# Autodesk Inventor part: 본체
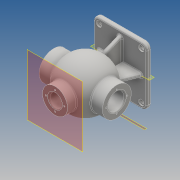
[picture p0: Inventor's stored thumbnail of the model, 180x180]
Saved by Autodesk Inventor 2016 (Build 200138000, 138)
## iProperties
Created: 2017-01
Part Number: 본체
Material: 일반
Document SubType Name: Modeling
Designer: Administrator
Density: 1 g/cm^3
Appearance: 기본값
Author: Administrator
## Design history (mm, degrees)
sketch "스케치1"
  geometry: L1 (57.5, 62.5)-(-57.5, 62.5); L2 (-57.5, 62.5)-(-57.5, -62.5); L3 (-57.5, -62.5)-(57.5, -62.5); L4 (57.5, -62.5)-(57.5, 62.5); L5 (57.5, 62.5)-(-57.5, -62.5); L6 (-57.5, 62.5)-(57.5, -62.5); 1 further point
  constraints: 12 end point, 2 midpoint, 2 parallel, 1 horizontal, 1 perpendicular
  dimensions: "d0" = 125 distance between parallel lines of L3 L1; "d1" = 115 distance between parallel lines of L2 L4
extrude "돌출1" new body sketch "스케치1" distance "d2" = 10; taper "d3" = 0 deg
fillet "모깎기2" dims "d5" = 3
fillet "모깎기3" dims "d6" = 12
node "작업 평면1"
sketch "스케치5"
  geometry: L1 (113.5, -75)-(-22.5, -75); L2 (113.5, -75)-(113.5, -106); L3 (-22.5, -75)-(-22.5, -106); L4 (45.5, 0)-(45.5, -185.881); L5 (113.5, -106)-(88.488, -106); L6 (-22.5, -106)-(2.512, -106); L7 (113.5, -92.5)-(84.778, -92.5); L8 (-22.5, -92.5)-(-6.5, -92.5); L9 (-6.5, -92.5)-(-6.5, -93.5); L10 (-6.5, -93.5)-(-4.75, -93.5); L11 (-4.75, -93.5)-(-4.75, -92.5); L12 (-4.75, -92.5)-(6.222, -92.5); L13 (0, 10)-(91, 10) reference; A1 r 53 centre (45.5, -75) between (2.512, -106) and (88.488, -106); A2 r 43 centre (45.5, -75) between (6.222, -92.5) and (84.778, -92.5)
  constraints: 24 end point, 5 horizontal, 4 point on circle, 4 point on line, 3 perpendicular, 3 vertical, 2 centre point, 1 coincident, 1 midpoint
  dimensions: "d22" = 136 distance between parallel lines of L3 L2; "d27" = 31 distance from line of L2.end L1; "d30" = 53 radius of A1; "d31" = 43 radius of A2; "d32" = 16 distance between parallel lines of L9 L3; "d33" = 17.5 distance between parallel lines of L1 L8; "d34" = 18.5 distance between parallel lines of L1 L10; "d35" = 17.5 distance between parallel lines of L7 L1; "d36" = 17.5 distance from line of L1 L12.end; "d37" = 31 distance between parallel lines of L6 L1; "d38" = 1.75 distance between parallel lines of L11 L9; "d39" = 85 distance between parallel lines of L13 L1
revolve "회전1" sketch "스케치5" stored, may be unused: angle "d40" = 90 deg
sketch "스케치6" dims "d41" = 48
  geometry: 3 further points
  constraints: 1 vertical alignment, 2 other
hole "구멍2" sketch "스케치6" at (0, -24) diameter "d42" = 3.242; stored, may be unused: countersink angle "d46" = 90 deg, drill point angle "d48" = 118 deg; dims "d43" = 16, "d44" = 12, "d45" = 3, "d47" = 19
node "작업 평면2"
sketch "스케치8"
  geometry: C1 r 27 at (0, 0); 1 further point
  constraints: 1 centre point, 1 coincident
  dimensions: "d61" = 54 diameter of C1
extrude "돌출2" join sketch "스케치8" stored distance "d62" = 10; taper "d63" = 0 deg
sketch "스케치9"
  geometry: C1 r 13 at (0, 0); 1 further point
  constraints: 1 centre point, 1 coincident
  dimensions: "d64" = 26 diameter of C1
extrude "돌출3" cut sketch "스케치9" distance "d65" = 50; taper "d66" = 0 deg
sketch "스케치10"
  geometry: A1 r 20 centre (0, 0) between (0, -20) and (0, 20); 3 further points
  constraints: 4 point on circle, 1 centre point, 1 coincident
  dimensions: "d67" = 40 diameter of A1
hole "구멍3" sketch "스케치10" at (0, -20), (20, 0), (0, 20), (-20, 0) diameter "d68" = 3.242; stored, may be unused: countersink angle "d72" = 90 deg, drill point angle "d74" = 118 deg; dims "d69" = 9, "d70" = 12, "d71" = 3, "d73" = 11
fillet "모깎기4" dims "d86" = 3
fillet "모깎기5" dims "d87" = 3
fillet "모깎기6" dims "d88" = 3
sketch "스케치13"
  geometry: A1 r 9 centre (45.5, 50.5) between (54.5, 50.5) and (45.5, 59.5) reference; 2 further points
  constraints: 1 coincident
hole "구멍4" sketch "스케치13" at (45.5, 50.5) diameter "d89" = 8; stored, may be unused: countersink angle "d93" = 90 deg, drill point angle "d95" = 118 deg; dims "d90" = 9, "d91" = 12, "d92" = 3, "d94" = 11
sketch "스케치14"
  geometry: L1 (47.5, 0)-(33.719, -34.109); L2 (-33.719, -34.109)-(-47.5, 0); L3 (51.5, 0)-(39.5, 0) reference; L4 (45.5, 0)-(-45.5, 0) reference; L5 (-39.5, 0)-(-51.5, 0) reference; L6 (-57.5, 3)-(-57.5, 7) reference; L7 (57.5, 7)-(57.5, 3) reference; A1 r 53 centre (0, -75) between (-42.113, -107.179) and (-42.113, -42.821) reference; 1 further point
  constraints: 4 end point, 2 point on circle, 2 point on line
  dimensions: "d102" = 10 distance from line of L6 L2.end; "d103" = 10 distance from line of L7 L1.start; "d104" = 22 deg angle of L1 L7; "d105" = 22 deg angle of L6 L2
extrude "돌출4" join sketch "스케치14" stored distance "d106" = 8; taper "d107" = 0 deg
sketch "스케치15"
  geometry: L1 (-35.992, 37.958)-(0, 52.5); L2 (0, 50.5)-(0, -50.5) reference; L3 (7, 62.5)-(3, 62.5) reference; 1 further point
  constraints: 2 end point, 1 point on line
  dimensions: "d108" = 10 distance from line of L3 L1.end; "d109" = 22 deg angle of L3 L1
feature "리브1" sketch "스케치15" dims "d110" = 1, "d111" = 8, "d112" = 0, "d113" = 0, "d114" = 1, "d115" = 1
sketch "스케치16"
  geometry: L1 (-35.514, -35.354)-(6.924, -52.5); L2 (3, -62.5)-(7, -62.5) reference; A1 r 53 centre (-75, 0) between (-119.753, -28.393) and (-119.753, 28.393) reference; 1 further point
  constraints: 2 end point, 1 point on circle
  dimensions: "d116" = 10 distance from line of L1.end L2; "d117" = 22 deg angle of L1 L2
feature "리브2" sketch "스케치16" dims "d118" = 1, "d119" = 8, "d120" = 0, "d121" = 0, "d122" = 1, "d123" = 1
fillet "모깎기7" dims "d124" = 3
fillet "모깎기8" dims "d125" = 3
sketch "스케치17"
  geometry: A1 r 22.5 centre (0, 0) between (0, -22.5) and (-22.5, 0); 3 further points
  constraints: 4 point on circle, 1 centre point
  dimensions: "d126" = 45 diameter of A1
hole "구멍5" sketch "스케치17" at (0, -22.5), (-22.5, 0), (0, 22.5), (22.5, 0) diameter "d127" = 3.242; stored, may be unused: countersink angle "d131" = 90 deg, drill point angle "d133" = 118 deg; dims "d128" = 12, "d129" = 12, "d130" = 3, "d132" = 15.8
node "작업 평면3"
sketch "스케치18"
  geometry: L1 (66.425, -140.002)-(24.575, -140.002); L2 (24.575, -140.002)-(24.575, -133.998); L3 (24.575, -133.998)-(66.425, -133.998); L4 (66.425, -133.998)-(66.425, -140.002); L5 (18.5, -147)-(72.5, -147) reference; 3 further points
  constraints: 2 midpoint, 2 other
  dimensions: "d136" = 10 distance from line of point (24.575, -137) L5; "d137" = 27 horizontal distance of L5.start point (45.5, -140.002)
feature "엠보싱1" sketch "스케치18" dims "d0" = 125, "d1" = 115, "d138" = 0.5, "d139" = 0
node "솔리드1"
pattern_linear "직사각형 패턴1" dims "d98" = 91, "d101" = 101
pattern_circular "원형 패턴2" dims angle "d141" = 360 deg
other parameters: "d134" = 38
